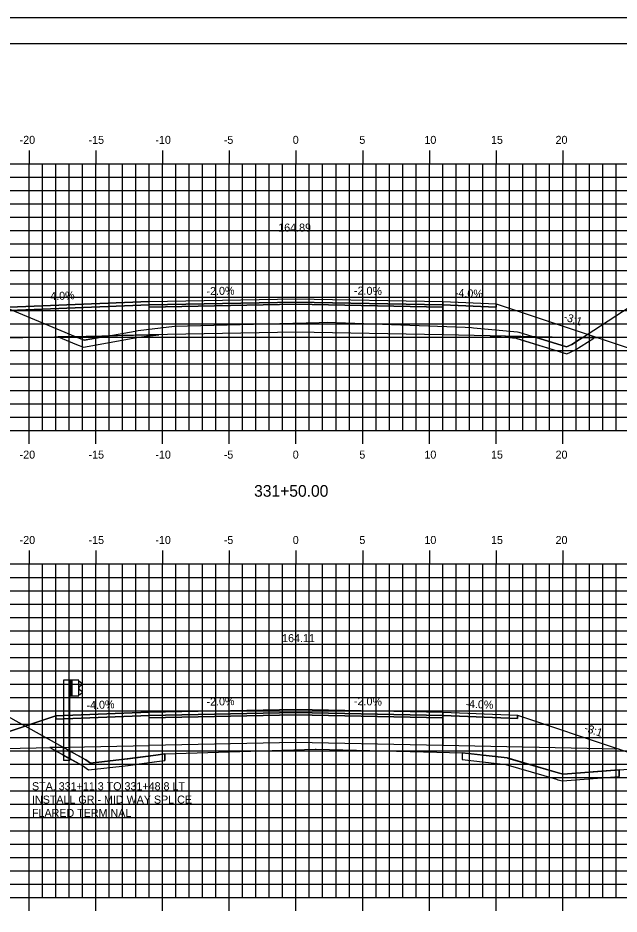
# Model space of a CAD drawing. Extents: x 1141424 to 1141594, y 608981 to 609091.
# Drawn here: x 1141486.4 to 1141531.5, y 609024.1 to 609091.3 of the extents above; entities that cross this region are included whole.
import ezdxf

# ---------------------------------------------------------------- set-up
doc = ezdxf.new("R2010")
doc.units = 0
for name, color, linetype in [('ANNOTATION', 7, 'Continuous'), ('BORDER', 7, 'Continuous'), ('D_Guardrail_Beam_Lt', 7, 'Continuous'), ('D_Roadway_Centerline', 7, 'Continuous'), ('D_Roadway_Centerline_Text', 7, 'Continuous'), ('D_Roadway_Edge_Shoulder', 7, 'Continuous'), ('D_Roadway_Edge_TW', 7, 'Continuous'), ('D_Roadway_Pavement', 7, 'Continuous'), ('D_Roadway_SlopeLines', 7, 'Continuous'), ('D_Roadway_SubGrade', 7, 'Continuous'), ('H_V ANNOTATION', 7, 'Continuous'), ('MAJOR', 7, 'Continuous'), ('MINOR', 7, 'Continuous'), ('PLOT BOUNDARY', 7, 'Continuous'), ('S_Roadway_Centerline', 7, 'Continuous'), ('SHADING', 7, 'Continuous')]:
    doc.layers.add(name, color=color, linetype=linetype)

msp = doc.modelspace()

# ---------------------------------------------------------------- linework, layer by layer
for points in [[(1141456.146, 609073.465), (1141457.396, 609073.337), (1141458.646, 609073.068), (1141459.896, 609072.656), (1141461.146, 609072.102), (1141473.145, 609066.102), (1141476.145, 609067.102), (1141483.295, 609069.486), (1141483.296, 609069.486), (1141496.271, 609070.005), (1141507.271, 609070.225), (1141518.271, 609070.005), (1141522.271, 609069.845), (1141529.994, 609067.271), (1141532.994, 609066.271), (1141540.103, 609069.825), (1141541.353, 609070.365), (1141542.603, 609070.736), (1141543.853, 609070.937), (1141545.103, 609070.968)], [(1141463.072, 609043.268), (1141478.738, 609035.436), (1141481.738, 609036.436), (1141489.27, 609038.946), (1141489.271, 609038.946), (1141496.271, 609039.226), (1141507.271, 609039.446), (1141518.271, 609039.226), (1141523.862, 609039.003), (1141531.484, 609036.462), (1141534.484, 609035.462), (1141535.293, 609035.192)]]:
    msp.add_lwpolyline(points)
at = {"layer": 'BORDER'}
msp.add_lwpolyline([(1141432.271, 608984.335), (1141592.271, 608984.335), (1141592.271, 609089.335), (1141432.271, 609089.335)], close=True, dxfattribs=at)
at = {"layer": 'D_Guardrail_Beam_Lt'}
for p, q in [((1141489.843, 609041.614), (1141489.843, 609035.614)), ((1141490.314, 609041.614), (1141489.843, 609041.614)), ((1141491.002, 609041.614), (1141490.314, 609041.614)), ((1141490.314, 609041.614), (1141490.314, 609040.447)), ((1141490.377, 609041.614), (1141490.377, 609040.447)), ((1141490.481, 609041.614), (1141490.481, 609040.447)), ((1141491.002, 609040.447), (1141491.002, 609041.614)), ((1141491.002, 609041.531), (1141491.076, 609041.516)), ((1141491.006, 609041.066), (1141491.006, 609040.996)), ((1141491.235, 609041.266), (1141491.04, 609041.13)), ((1141491.04, 609040.931), (1141491.235, 609040.795)), ((1141491.092, 609041.51), (1141491.235, 609041.41)), ((1141490.314, 609040.447), (1141491.002, 609040.447)), ((1141490.335, 609035.614), (1141490.335, 609040.447)), ((1141491.076, 609040.545), (1141491.002, 609040.531)), ((1141491.235, 609040.652), (1141491.092, 609040.552)), ((1141490.335, 609035.614), (1141489.843, 609035.614))]:
    msp.add_line(p, q, dxfattribs=at)
for centre, major_axis, start_param, end_param in [((1141491.085, 609041.066), (-0.0789, 0), 5.323254, 6.283185), ((1141491.085, 609040.996), (-0.0789, 0), 6.283185, 7.243116), ((1141491.068, 609041.476), (0.0417, 0), 0.959931, 1.376053), ((1141491.185, 609041.338), (0.0877, 0), 5.323254, 7.243116), ((1141491.068, 609040.586), (0.0417, 0), 4.907132, 5.323254), ((1141491.185, 609040.724), (0.0877, 0), 5.323254, 7.243116)]:
    msp.add_ellipse(centre, major_axis=major_axis, ratio=0.995501, start_param=start_param, end_param=end_param, dxfattribs=at)
at = {"layer": 'D_Roadway_Edge_Shoulder'}
for points in [[(1141496.271, 609070.005), (1141483.296, 609069.486), (1141483.296, 609069.236), (1141496.271, 609069.755)], [(1141518.271, 609070.005), (1141522.271, 609069.845), (1141522.271, 609069.595), (1141518.271, 609069.755)], [(1141496.271, 609039.226), (1141489.271, 609038.946), (1141489.271, 609038.696), (1141496.271, 609038.976)], [(1141518.271, 609039.226), (1141523.862, 609039.003), (1141523.862, 609038.753), (1141518.271, 609038.976)]]:
    msp.add_lwpolyline(points, close=True, dxfattribs=at)
at = {"layer": 'D_Roadway_Edge_TW'}
for points in [[(1141496.271, 609069.755), (1141496.271, 609070.005), (1141507.271, 609070.225), (1141518.271, 609070.005), (1141518.271, 609069.755), (1141507.271, 609069.975)], [(1141496.271, 609038.976), (1141496.271, 609039.226), (1141507.271, 609039.446), (1141518.271, 609039.226), (1141518.271, 609038.976), (1141507.271, 609039.196)]]:
    msp.add_lwpolyline(points, close=True, dxfattribs=at)
at = {"layer": 'D_Roadway_Pavement'}
for points in [[(1141496.271, 609069.588), (1141496.271, 609069.755), (1141507.271, 609069.975), (1141518.271, 609069.755), (1141518.271, 609069.588), (1141507.271, 609069.808)], [(1141496.271, 609038.81), (1141496.271, 609038.976), (1141507.271, 609039.196), (1141518.271, 609038.976), (1141518.271, 609038.81), (1141507.271, 609039.03)]]:
    msp.add_lwpolyline(points, close=True, dxfattribs=at)
at = {"layer": 'D_Roadway_SlopeLines'}
for p, q in [((1141497.432, 609036.106), (1141497.432, 609035.606)), ((1141519.734, 609036.183), (1141519.734, 609035.683)), ((1141531.484, 609034.905), (1141531.484, 609034.404))]:
    msp.add_line(p, q, dxfattribs=at)
for points in [[(1141489.444, 609067.368), (1141490.824, 609066.791), (1141491.341, 609066.588), (1141495.344, 609067.308), (1141495.424, 609067.332), (1141495.495, 609067.339), (1141496.99, 609067.519)], [(1141489.444, 609067.368), (1141490.824, 609066.791), (1141491.341, 609066.588), (1141495.344, 609067.308), (1141495.424, 609067.332), (1141495.495, 609067.339), (1141496.99, 609067.519)], [(1141521.827, 609067.434), (1141523.771, 609067.26), (1141523.81, 609067.245), (1141527.576, 609066.093), (1141528.18, 609066.36), (1141529.596, 609067.278)], [(1141521.827, 609067.434), (1141523.771, 609067.26), (1141523.81, 609067.245), (1141527.576, 609066.093), (1141528.18, 609066.36), (1141529.596, 609067.278)], [(1141529.994, 609067.271), (1141532.994, 609066.271)], [(1141488.835, 609036.578), (1141491.262, 609035.222), (1141491.731, 609034.896), (1141494.702, 609035.225), (1141494.773, 609035.243), (1141496.844, 609035.517), (1141497.432, 609035.601)], [(1141519.734, 609035.679), (1141522.994, 609035.301), (1141526.789, 609034.196), (1141526.902, 609034.161), (1141527.251, 609034.085), (1141531.484, 609034.404)]]:
    msp.add_lwpolyline(points, dxfattribs=at)
at = {"layer": 'D_Roadway_SubGrade'}
for points in [[(1141496.271, 609067.505), (1141496.271, 609069.588), (1141507.271, 609069.808), (1141518.271, 609069.588), (1141518.271, 609067.505), (1141507.271, 609067.725)], [(1141518.271, 609069.588), (1141518.271, 609069.755), (1141522.271, 609069.595), (1141522.271, 609069.845), (1141522.271, 609069.845), (1141529.994, 609067.271), (1141518.271, 609067.505)], [(1141496.271, 609069.588), (1141496.271, 609069.755), (1141483.296, 609069.236), (1141483.296, 609069.486), (1141483.295, 609069.486), (1141476.145, 609067.102), (1141496.271, 609067.505)], [(1141496.271, 609038.81), (1141496.271, 609038.976), (1141489.271, 609038.696), (1141489.271, 609038.946), (1141489.27, 609038.946), (1141481.738, 609036.436), (1141496.271, 609036.726)], [(1141496.271, 609036.726), (1141496.271, 609038.81), (1141507.271, 609039.03), (1141518.271, 609038.81), (1141518.271, 609036.726), (1141507.271, 609036.946)], [(1141518.271, 609038.81), (1141518.271, 609038.976), (1141523.862, 609038.753), (1141523.862, 609039.003), (1141523.862, 609039.003), (1141531.484, 609036.462), (1141518.271, 609036.726)]]:
    msp.add_lwpolyline(points, close=True, dxfattribs=at)
at = {"layer": 'MAJOR'}
for p, q in [((1141487.271, 609081.337), (1141487.271, 609080.335)), ((1141492.271, 609081.337), (1141492.271, 609080.335)), ((1141497.271, 609081.337), (1141497.271, 609080.335)), ((1141502.271, 609081.337), (1141502.271, 609080.335)), ((1141507.271, 609081.337), (1141507.271, 609080.335)), ((1141512.271, 609081.337), (1141512.271, 609080.335)), ((1141517.271, 609081.337), (1141517.271, 609080.335)), ((1141522.271, 609081.337), (1141522.271, 609080.335)), ((1141527.271, 609081.337), (1141527.271, 609080.335)), ((1141437.271, 609080.335), (1141577.271, 609080.335)), ((1141437.271, 609080.335), (1141577.271, 609080.335)), ((1141487.271, 609060.335), (1141487.271, 609080.335)), ((1141492.271, 609060.335), (1141492.271, 609080.335)), ((1141497.271, 609060.335), (1141497.271, 609080.335)), ((1141502.271, 609060.335), (1141502.271, 609080.335)), ((1141507.271, 609060.335), (1141507.271, 609080.335)), ((1141512.271, 609060.335), (1141512.271, 609080.335)), ((1141517.271, 609060.335), (1141517.271, 609080.335)), ((1141522.271, 609060.335), (1141522.271, 609080.335)), ((1141527.271, 609060.335), (1141527.271, 609080.335)), ((1141437.271, 609075.335), (1141577.271, 609075.335)), ((1141437.271, 609070.335), (1141577.271, 609070.335)), ((1141437.271, 609065.335), (1141577.271, 609065.335)), ((1141437.271, 609060.335), (1141577.271, 609060.335)), ((1141437.271, 609060.335), (1141577.271, 609060.335)), ((1141487.271, 609059.333), (1141487.271, 609060.335)), ((1141492.271, 609059.333), (1141492.271, 609060.335)), ((1141497.271, 609059.333), (1141497.271, 609060.335)), ((1141502.271, 609059.333), (1141502.271, 609060.335)), ((1141507.271, 609059.333), (1141507.271, 609060.335)), ((1141512.271, 609059.333), (1141512.271, 609060.335)), ((1141517.271, 609059.333), (1141517.271, 609060.335)), ((1141522.271, 609059.333), (1141522.271, 609060.335)), ((1141527.271, 609059.333), (1141527.271, 609060.335)), ((1141487.271, 609051.337), (1141487.271, 609050.335)), ((1141492.271, 609051.337), (1141492.271, 609050.335)), ((1141497.271, 609051.337), (1141497.271, 609050.335)), ((1141502.271, 609051.337), (1141502.271, 609050.335)), ((1141507.271, 609051.337), (1141507.271, 609050.335)), ((1141512.271, 609051.337), (1141512.271, 609050.335)), ((1141517.271, 609051.337), (1141517.271, 609050.335)), ((1141522.271, 609051.337), (1141522.271, 609050.335)), ((1141527.271, 609051.337), (1141527.271, 609050.335)), ((1141437.271, 609050.335), (1141577.271, 609050.335)), ((1141437.271, 609050.335), (1141577.271, 609050.335)), ((1141487.271, 609025.335), (1141487.271, 609050.335)), ((1141492.271, 609025.335), (1141492.271, 609050.335)), ((1141497.271, 609025.335), (1141497.271, 609050.335)), ((1141502.271, 609025.335), (1141502.271, 609050.335)), ((1141507.271, 609025.335), (1141507.271, 609050.335)), ((1141512.271, 609025.335), (1141512.271, 609050.335)), ((1141517.271, 609025.335), (1141517.271, 609050.335)), ((1141522.271, 609025.335), (1141522.271, 609050.335)), ((1141527.271, 609025.335), (1141527.271, 609050.335)), ((1141437.271, 609045.335), (1141577.271, 609045.335)), ((1141437.271, 609040.335), (1141577.271, 609040.335)), ((1141437.271, 609035.335), (1141577.271, 609035.335)), ((1141437.271, 609030.335), (1141577.271, 609030.335)), ((1141437.271, 609025.335), (1141577.271, 609025.335)), ((1141437.271, 609025.335), (1141577.271, 609025.335)), ((1141487.271, 609024.333), (1141487.271, 609025.335)), ((1141492.271, 609024.333), (1141492.271, 609025.335)), ((1141497.271, 609024.333), (1141497.271, 609025.335)), ((1141502.271, 609024.333), (1141502.271, 609025.335)), ((1141507.271, 609024.333), (1141507.271, 609025.335)), ((1141512.271, 609024.333), (1141512.271, 609025.335)), ((1141517.271, 609024.333), (1141517.271, 609025.335)), ((1141522.271, 609024.333), (1141522.271, 609025.335)), ((1141527.271, 609024.333), (1141527.271, 609025.335))]:
    msp.add_line(p, q, dxfattribs=at)
at = {"layer": 'MINOR'}
for p, q in [((1141488.271, 609060.335), (1141488.271, 609080.335)), ((1141489.271, 609060.335), (1141489.271, 609080.335)), ((1141490.271, 609060.335), (1141490.271, 609080.335)), ((1141491.271, 609060.335), (1141491.271, 609080.335)), ((1141493.271, 609060.335), (1141493.271, 609080.335)), ((1141494.271, 609060.335), (1141494.271, 609080.335)), ((1141495.271, 609060.335), (1141495.271, 609080.335)), ((1141496.271, 609060.335), (1141496.271, 609080.335)), ((1141498.271, 609060.335), (1141498.271, 609080.335)), ((1141499.271, 609060.335), (1141499.271, 609080.335)), ((1141500.271, 609060.335), (1141500.271, 609080.335)), ((1141501.271, 609060.335), (1141501.271, 609080.335)), ((1141503.271, 609060.335), (1141503.271, 609080.335)), ((1141504.271, 609060.335), (1141504.271, 609080.335)), ((1141505.271, 609060.335), (1141505.271, 609080.335)), ((1141506.271, 609060.335), (1141506.271, 609080.335)), ((1141508.271, 609060.335), (1141508.271, 609080.335)), ((1141509.271, 609060.335), (1141509.271, 609080.335)), ((1141510.271, 609060.335), (1141510.271, 609080.335)), ((1141511.271, 609060.335), (1141511.271, 609080.335)), ((1141513.271, 609060.335), (1141513.271, 609080.335)), ((1141514.271, 609060.335), (1141514.271, 609080.335)), ((1141515.271, 609060.335), (1141515.271, 609080.335)), ((1141516.271, 609060.335), (1141516.271, 609080.335)), ((1141518.271, 609060.335), (1141518.271, 609080.335)), ((1141519.271, 609060.335), (1141519.271, 609080.335)), ((1141520.271, 609060.335), (1141520.271, 609080.335)), ((1141521.271, 609060.335), (1141521.271, 609080.335)), ((1141523.271, 609060.335), (1141523.271, 609080.335)), ((1141524.271, 609060.335), (1141524.271, 609080.335)), ((1141525.271, 609060.335), (1141525.271, 609080.335)), ((1141526.271, 609060.335), (1141526.271, 609080.335)), ((1141528.271, 609060.335), (1141528.271, 609080.335)), ((1141529.271, 609060.335), (1141529.271, 609080.335)), ((1141530.271, 609060.335), (1141530.271, 609080.335)), ((1141531.271, 609060.335), (1141531.271, 609080.335)), ((1141437.271, 609079.335), (1141577.271, 609079.335)), ((1141437.271, 609078.335), (1141577.271, 609078.335)), ((1141437.271, 609077.335), (1141577.271, 609077.335)), ((1141437.271, 609076.335), (1141577.271, 609076.335)), ((1141437.271, 609074.335), (1141577.271, 609074.335)), ((1141437.271, 609073.335), (1141577.271, 609073.335)), ((1141437.271, 609072.335), (1141577.271, 609072.335)), ((1141437.271, 609071.335), (1141577.271, 609071.335)), ((1141437.271, 609069.335), (1141577.271, 609069.335)), ((1141437.271, 609068.335), (1141577.271, 609068.335)), ((1141437.271, 609067.335), (1141577.271, 609067.335)), ((1141437.271, 609066.335), (1141577.271, 609066.335)), ((1141437.271, 609064.335), (1141577.271, 609064.335)), ((1141437.271, 609063.335), (1141577.271, 609063.335)), ((1141437.271, 609062.335), (1141577.271, 609062.335)), ((1141437.271, 609061.335), (1141577.271, 609061.335)), ((1141488.271, 609025.335), (1141488.271, 609050.335)), ((1141489.271, 609025.335), (1141489.271, 609050.335)), ((1141490.271, 609025.335), (1141490.271, 609050.335)), ((1141491.271, 609025.335), (1141491.271, 609050.335)), ((1141493.271, 609025.335), (1141493.271, 609050.335)), ((1141494.271, 609025.335), (1141494.271, 609050.335)), ((1141495.271, 609025.335), (1141495.271, 609050.335)), ((1141496.271, 609025.335), (1141496.271, 609050.335)), ((1141498.271, 609025.335), (1141498.271, 609050.335)), ((1141499.271, 609025.335), (1141499.271, 609050.335)), ((1141500.271, 609025.335), (1141500.271, 609050.335)), ((1141501.271, 609025.335), (1141501.271, 609050.335)), ((1141503.271, 609025.335), (1141503.271, 609050.335)), ((1141504.271, 609025.335), (1141504.271, 609050.335)), ((1141505.271, 609025.335), (1141505.271, 609050.335)), ((1141506.271, 609025.335), (1141506.271, 609050.335)), ((1141508.271, 609025.335), (1141508.271, 609050.335)), ((1141509.271, 609025.335), (1141509.271, 609050.335)), ((1141510.271, 609025.335), (1141510.271, 609050.335)), ((1141511.271, 609025.335), (1141511.271, 609050.335)), ((1141513.271, 609025.335), (1141513.271, 609050.335)), ((1141514.271, 609025.335), (1141514.271, 609050.335)), ((1141515.271, 609025.335), (1141515.271, 609050.335)), ((1141516.271, 609025.335), (1141516.271, 609050.335)), ((1141518.271, 609025.335), (1141518.271, 609050.335)), ((1141519.271, 609025.335), (1141519.271, 609050.335)), ((1141520.271, 609025.335), (1141520.271, 609050.335)), ((1141521.271, 609025.335), (1141521.271, 609050.335)), ((1141523.271, 609025.335), (1141523.271, 609050.335)), ((1141524.271, 609025.335), (1141524.271, 609050.335)), ((1141525.271, 609025.335), (1141525.271, 609050.335)), ((1141526.271, 609025.335), (1141526.271, 609050.335)), ((1141528.271, 609025.335), (1141528.271, 609050.335)), ((1141529.271, 609025.335), (1141529.271, 609050.335)), ((1141530.271, 609025.335), (1141530.271, 609050.335)), ((1141531.271, 609025.335), (1141531.271, 609050.335)), ((1141437.271, 609049.335), (1141577.271, 609049.335)), ((1141437.271, 609048.335), (1141577.271, 609048.335)), ((1141437.271, 609047.335), (1141577.271, 609047.335)), ((1141437.271, 609046.335), (1141577.271, 609046.335)), ((1141437.271, 609044.335), (1141577.271, 609044.335)), ((1141437.271, 609043.335), (1141577.271, 609043.335)), ((1141437.271, 609042.335), (1141577.271, 609042.335)), ((1141437.271, 609041.335), (1141577.271, 609041.335)), ((1141437.271, 609039.335), (1141577.271, 609039.335)), ((1141437.271, 609038.335), (1141577.271, 609038.335)), ((1141437.271, 609037.335), (1141577.271, 609037.335)), ((1141437.271, 609036.335), (1141577.271, 609036.335)), ((1141437.271, 609034.335), (1141577.271, 609034.335)), ((1141437.271, 609033.335), (1141577.271, 609033.335)), ((1141437.271, 609032.335), (1141577.271, 609032.335)), ((1141437.271, 609031.335), (1141577.271, 609031.335)), ((1141437.271, 609029.335), (1141577.271, 609029.335)), ((1141437.271, 609028.335), (1141577.271, 609028.335)), ((1141437.271, 609027.335), (1141577.271, 609027.335)), ((1141437.271, 609026.335), (1141577.271, 609026.335))]:
    msp.add_line(p, q, dxfattribs=at)
at = {"layer": 'PLOT BOUNDARY'}
msp.add_lwpolyline([(1141424.178, 608981.276), (1141594.178, 608981.276), (1141594.178, 609091.276), (1141424.178, 609091.276)], close=True, dxfattribs=at)
at = {"layer": 'S_Roadway_Centerline'}
for points in [[(1141454.537, 609073.535), (1141458.051, 609073.382), (1141478.858, 609072.336), (1141491.012, 609067.255), (1141491.392, 609067.105), (1141495.226, 609067.794), (1141495.325, 609067.825), (1141495.441, 609067.836), (1141498.174, 609068.166), (1141509.012, 609068.453), (1141509.602, 609068.468), (1141519.951, 609068.08), (1141520.424, 609068.064), (1141520.58, 609068.047), (1141523.884, 609067.752), (1141523.972, 609067.719), (1141527.544, 609066.625), (1141527.941, 609066.801), (1141535.037, 609071.404), (1141544.971, 609070.972), (1141552.331, 609070.764)], [(1141460.253, 609043.541), (1141476.77, 609041.777), (1141482.141, 609040.888), (1141491.527, 609035.647), (1141491.862, 609035.413), (1141494.612, 609035.718), (1141494.678, 609035.735), (1141496.776, 609036.013), (1141497.432, 609036.106), (1141508.706, 609036.443), (1141508.794, 609036.445), (1141517.825, 609036.227), (1141519.734, 609036.183), (1141519.739, 609036.182), (1141523.102, 609035.791), (1141523.112, 609035.787), (1141526.932, 609034.675), (1141527.029, 609034.645), (1141527.286, 609034.589), (1141536.73, 609035.3), (1141543.797, 609034.883), (1141551.696, 609034.212), (1141577.271, 609030.888)]]:
    msp.add_lwpolyline(points, dxfattribs=at)
at = {"layer": 'SHADING'}
for p, q in [((1141490.681, 609067.393), (1141489.444, 609067.368)), ((1141489.444, 609067.368), (1141490.824, 609066.791)), ((1141491.341, 609066.588), (1141495.344, 609067.308)), ((1141496.271, 609067.505), (1141493.283, 609067.445)), ((1141496.99, 609067.519), (1141496.271, 609067.505)), ((1141496.279, 609067.434), (1141496.99, 609067.519)), ((1141525.132, 609067.368), (1141521.827, 609067.434)), ((1141528.18, 609066.36), (1141529.596, 609067.278)), ((1141529.596, 609067.278), (1141528.704, 609067.296)), ((1141490.824, 609066.791), (1141491.341, 609066.588)), ((1141489.825, 609036.597), (1141488.835, 609036.578)), ((1141488.835, 609036.578), (1141489.843, 609036.014)), ((1141489.843, 609036.587), (1141489.825, 609036.597)), ((1141490.335, 609036.312), (1141489.843, 609036.587)), ((1141489.843, 609036.587), (1141489.843, 609036.014)), ((1141489.843, 609036.014), (1141489.843, 609036.587)), ((1141490.335, 609036.312), (1141490.335, 609035.74)), ((1141490.335, 609035.74), (1141490.335, 609036.312)), ((1141489.843, 609036.014), (1141490.335, 609035.74)), ((1141490.335, 609035.74), (1141491.262, 609035.222)), ((1141497.432, 609035.606), (1141497.432, 609036.106)), ((1141519.734, 609036.183), (1141519.734, 609035.683)), ((1141531.484, 609034.404), (1141531.484, 609034.905))]:
    msp.add_line(p, q, dxfattribs=at)
for points in [[(1141493.283, 609067.445), (1141491.392, 609067.105), (1141491.012, 609067.255), (1141490.681, 609067.393)], [(1141495.344, 609067.308), (1141495.495, 609067.339), (1141496.279, 609067.434)], [(1141496.279, 609067.434), (1141496.271, 609067.505)], [(1141496.271, 609067.505), (1141496.279, 609067.434)], [(1141521.827, 609067.434), (1141523.771, 609067.26), (1141527.576, 609066.093), (1141528.18, 609066.36)], [(1141528.704, 609067.296), (1141527.941, 609066.801), (1141527.544, 609066.625), (1141525.132, 609067.368)], [(1141497.432, 609036.106), (1141496.776, 609036.013), (1141494.612, 609035.718), (1141491.862, 609035.413), (1141491.527, 609035.647), (1141490.335, 609036.312)], [(1141491.262, 609035.222), (1141491.731, 609034.896), (1141494.702, 609035.225), (1141496.844, 609035.517), (1141497.432, 609035.606)], [(1141531.484, 609034.905), (1141527.286, 609034.589), (1141526.932, 609034.675), (1141523.102, 609035.791), (1141519.734, 609036.183)], [(1141519.734, 609035.683), (1141522.994, 609035.301), (1141526.789, 609034.196), (1141526.902, 609034.161), (1141527.251, 609034.085), (1141531.484, 609034.404)]]:
    msp.add_lwpolyline(points, dxfattribs=at)

# ---------------------------------------------------------------- texts
at = {"layer": 'ANNOTATION'}
for s, rotation, p in [('-2.0%', 1.14576, (1141500.574, 609070.491)), ('-2.0%', 358.85424, (1141511.614, 609070.538)), ('-4.0%', 2.29061, (1141488.599, 609070.099)), ('-4.0%', 357.70939, (1141519.167, 609070.37)), ('-3:1', 341.56521, (1141527.282, 609068.629)), ('-2.0%', 1.14576, (1141500.574, 609039.713)), ('-2.0%', 358.85424, (1141511.614, 609039.76)), ('-4.0%', 2.29061, (1141491.587, 609039.44)), ('-4.0%', 357.70939, (1141519.962, 609039.56)), ('-3:1', 341.56522, (1141528.822, 609037.803))]:
    msp.add_text(s, height=0.6, rotation=rotation, dxfattribs=at).set_placement(p)
for s, p in [('STA. 331+11.3 TO 331+48.8 LT', (1141487.488, 609033.375)), ('INSTALL GR - MID WAY SPLICE', (1141487.488, 609032.373)), ('FLARED TERMINAL', (1141487.488, 609031.371))]:
    msp.add_text(s, height=0.6, dxfattribs=at).set_placement(p)
at = {"layer": 'D_Roadway_Centerline'}
for s, p in [('C', (1141507.265, 609070.225)), ('C', (1141507.265, 609070.225)), ('L', (1141507.271, 609070.218)), ('L', (1141507.271, 609070.218)), ('C', (1141507.265, 609039.446)), ('C', (1141507.265, 609039.446)), ('L', (1141507.271, 609039.439)), ('L', (1141507.271, 609039.439))]:
    msp.add_text(s, height=0.0146, dxfattribs=at).set_placement(p)
at = {"layer": 'D_Roadway_Centerline_Text'}
for s, p in [('164.89', (1141505.944, 609075.257)), ('164.11', (1141506.233, 609044.478))]:
    msp.add_text(s, height=0.6, dxfattribs=at).set_placement(p)
at = {"layer": 'H_V ANNOTATION'}
for s, height, p in [('-20', 0.6, (1141486.564, 609081.835)), ('-15', 0.6, (1141491.728, 609081.835)), ('-10', 0.6, (1141496.736, 609081.835)), ('-5', 0.6, (1141501.861, 609081.835)), ('0', 0.6, (1141507.03, 609081.835)), ('5', 0.6, (1141512.022, 609081.835)), ('10', 0.6, (1141516.896, 609081.835)), ('15', 0.6, (1141521.888, 609081.835)), ('20', 0.6, (1141526.725, 609081.835)), ('-20', 0.6, (1141486.564, 609058.235)), ('-15', 0.6, (1141491.728, 609058.235)), ('-10', 0.6, (1141496.736, 609058.235)), ('-5', 0.6, (1141501.861, 609058.235)), ('0', 0.6, (1141507.03, 609058.235)), ('5', 0.6, (1141512.022, 609058.235)), ('10', 0.6, (1141516.896, 609058.235)), ('15', 0.6, (1141521.888, 609058.235)), ('20', 0.6, (1141526.725, 609058.235)), ('331+50.00', 0.875, (1141504.134, 609055.378)), ('-20', 0.6, (1141486.564, 609051.835)), ('-15', 0.6, (1141491.728, 609051.835)), ('-10', 0.6, (1141496.736, 609051.835)), ('-5', 0.6, (1141501.861, 609051.835)), ('0', 0.6, (1141507.03, 609051.835)), ('5', 0.6, (1141512.022, 609051.835)), ('10', 0.6, (1141516.896, 609051.835)), ('15', 0.6, (1141521.888, 609051.835)), ('20', 0.6, (1141526.725, 609051.835))]:
    msp.add_text(s, height=height, dxfattribs=at).set_placement(p)
at = {"layer": 'S_Roadway_Centerline'}
for s, p in [('C', (1141509.597, 609068.468)), ('L', (1141509.602, 609068.46)), ('C', (1141508.789, 609036.445)), ('L', (1141508.794, 609036.438))]:
    msp.add_text(s, height=0.0146, dxfattribs=at).set_placement(p)

doc.saveas('drawing.dxf')
